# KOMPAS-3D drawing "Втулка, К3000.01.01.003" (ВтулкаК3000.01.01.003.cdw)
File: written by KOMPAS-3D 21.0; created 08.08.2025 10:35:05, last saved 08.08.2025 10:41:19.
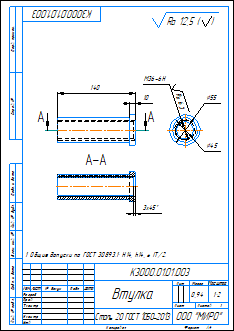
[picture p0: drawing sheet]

Sheet 1: A4, portrait

Document properties: Автор: admin; Знак неуказанной шероховатости: 4; Параметр неуказанной шероховатости: Ra 12,5; Масса: 0.941153; Полное имя файла: ..\Из трубы\Втулка.m3d

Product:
- Part/product: Втулка  | designation К3000.01.01.003
    Материал: Сталь 20 ГОСТ 1050-2013 (density 7859 kg/m3)
    Масса: 0.941153

Title block, sheet 1: Наименование: Втулка; designation: К3000.01.01.003; Материал: Сталь 20 ГОСТ 1050-2013; Масса: 0,94; Количество листов документа: 1; organisation: ООО "МИРО"; Форматы листов документа: A4; stored path: C:\Users\ShavarinML\Desktop\Стапель\2D\ВтулкаК3000.01.01.003.cdw

Views: Спереди 1, Спереди, Проекционный вид 3, Разрез А-А
Referenced files in C:\Users\ShavarinML\Desktop\Стапель\Из трубы\: Втулка.m3d
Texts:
  Ra 6,3
  Ra 12,5
  Ra 12,5 ( )
  К3000.01.01.003 Втулка
Dimensions and other numbers on the sheet: 140; 10; 55; 45; -6H; 36; 3; 1:2; 1; 0,94

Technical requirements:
  Общие допуски по ГОСТ 30893.1: H14, h14,   IT/2.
